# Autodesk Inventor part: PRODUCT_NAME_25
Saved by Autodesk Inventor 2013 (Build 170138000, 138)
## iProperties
Created: 2012-12
Part Number: PRODUCT_NAME_25
Material: Générique
Document SubType Name: Modeling
Designer: jost thierry
Density: 1 g/cm^3
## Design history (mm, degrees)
node "PRODUCT_NAME_251"
node "PRODUCT_NAME_25"
node "Base1"
